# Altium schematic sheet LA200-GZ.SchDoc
size A1
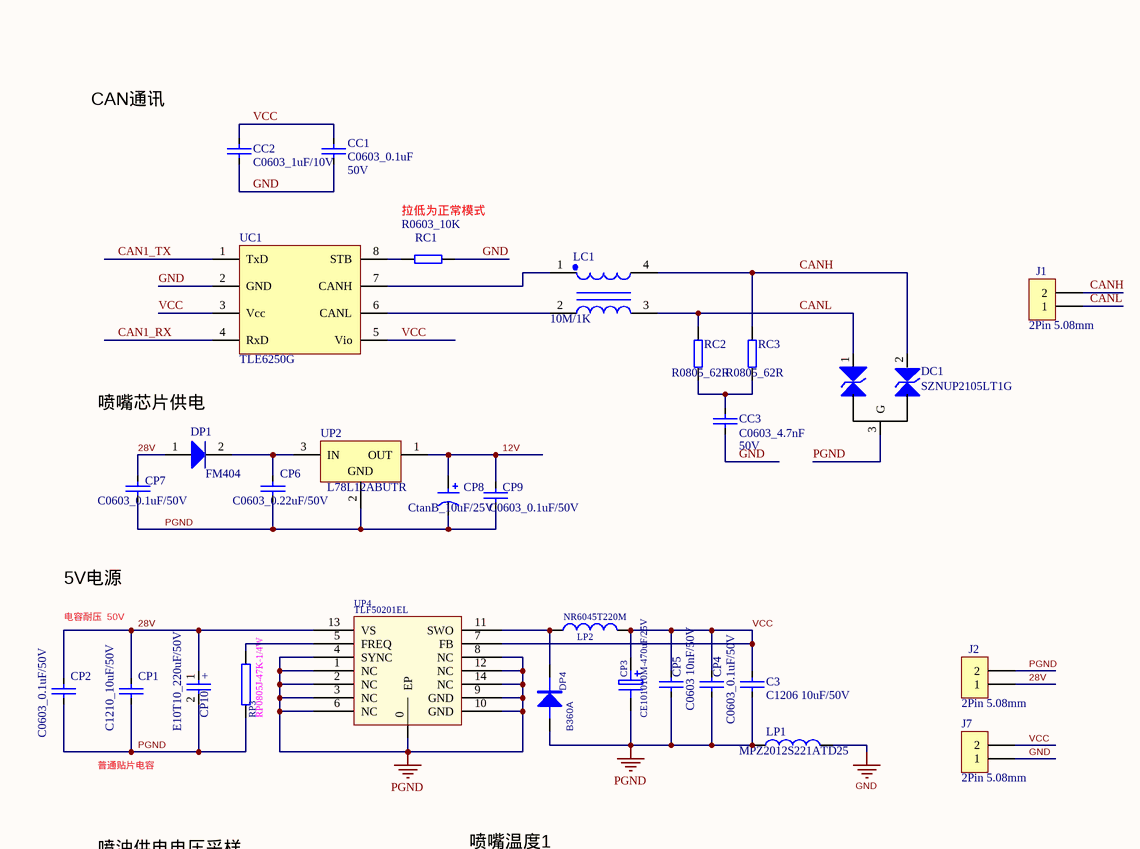
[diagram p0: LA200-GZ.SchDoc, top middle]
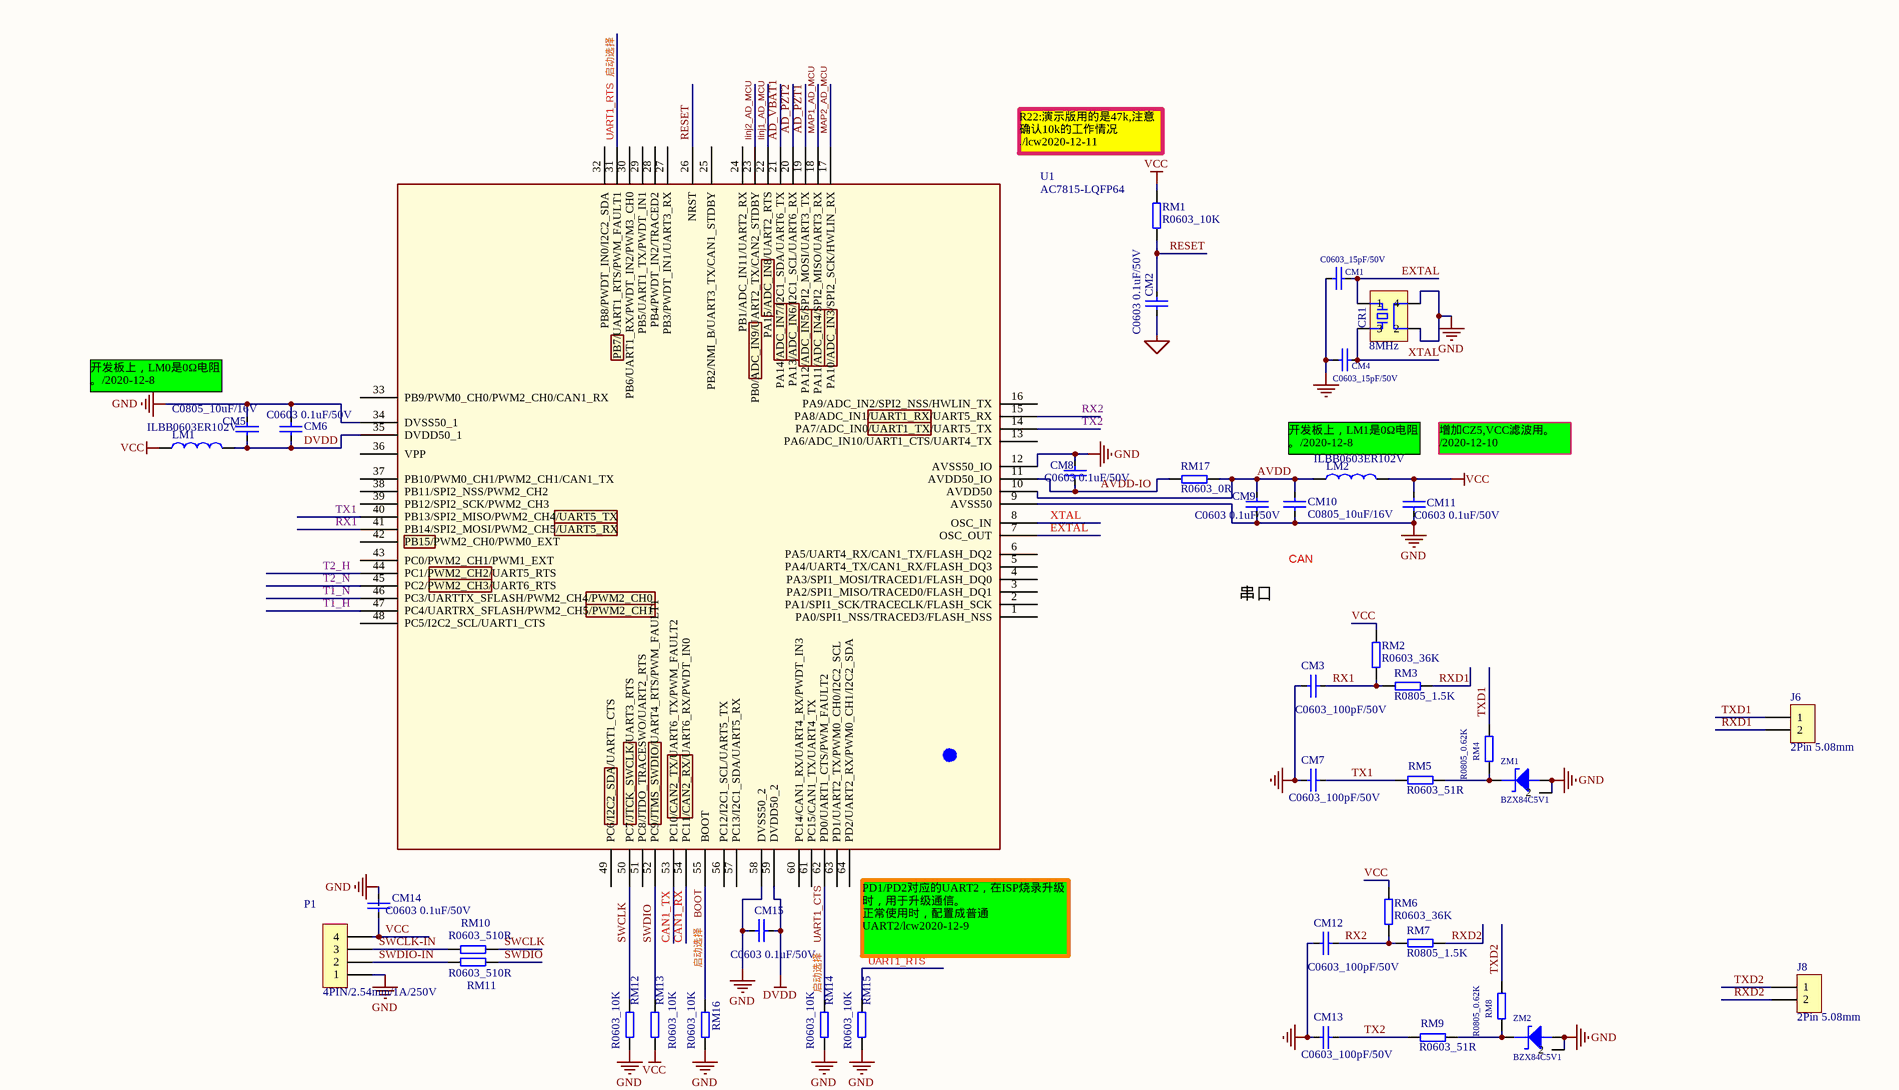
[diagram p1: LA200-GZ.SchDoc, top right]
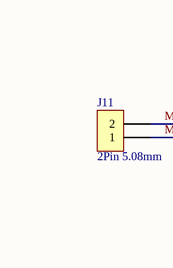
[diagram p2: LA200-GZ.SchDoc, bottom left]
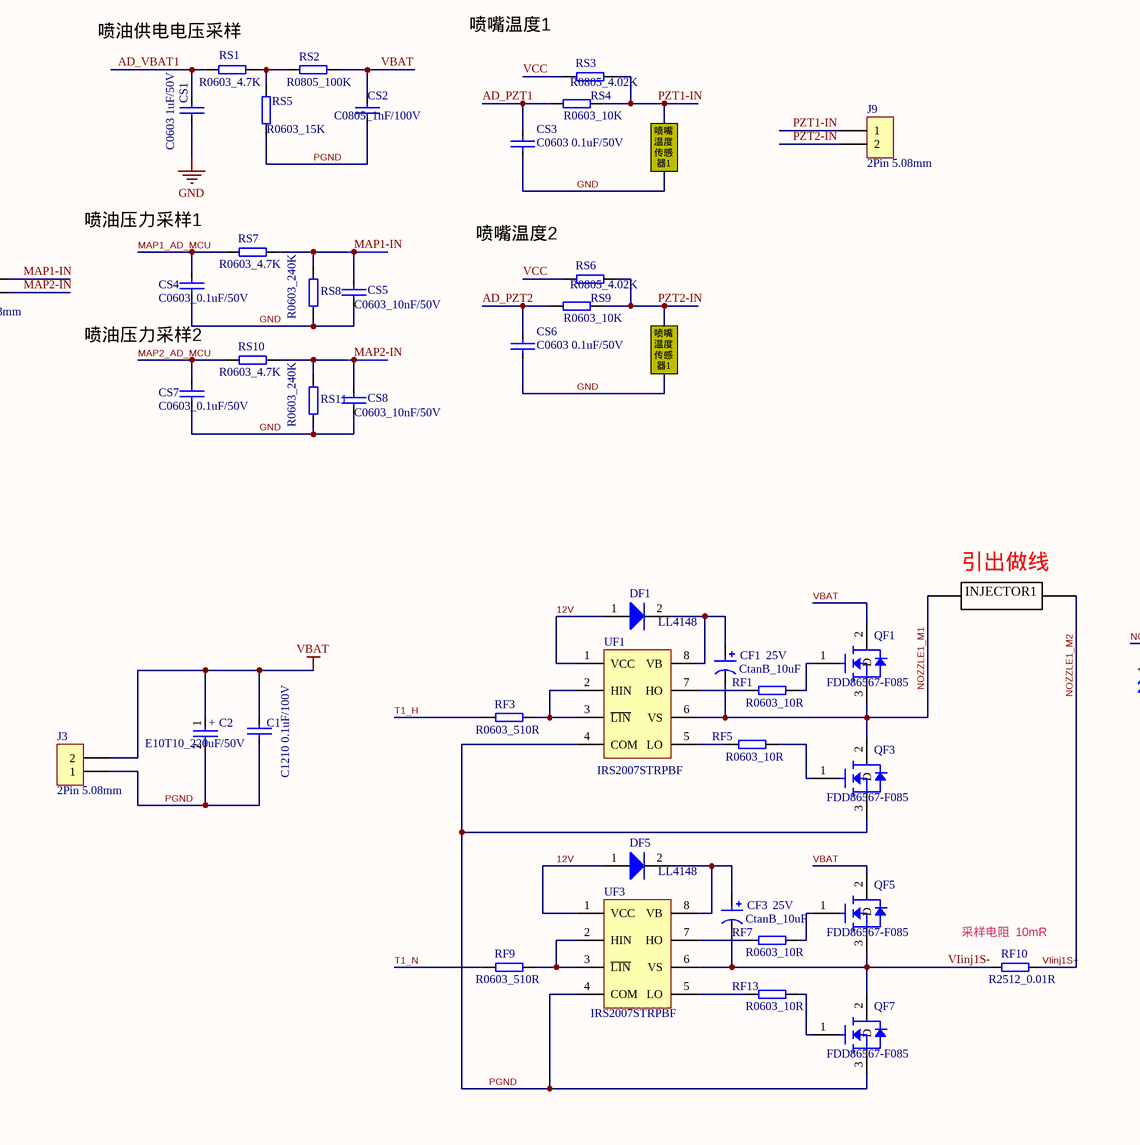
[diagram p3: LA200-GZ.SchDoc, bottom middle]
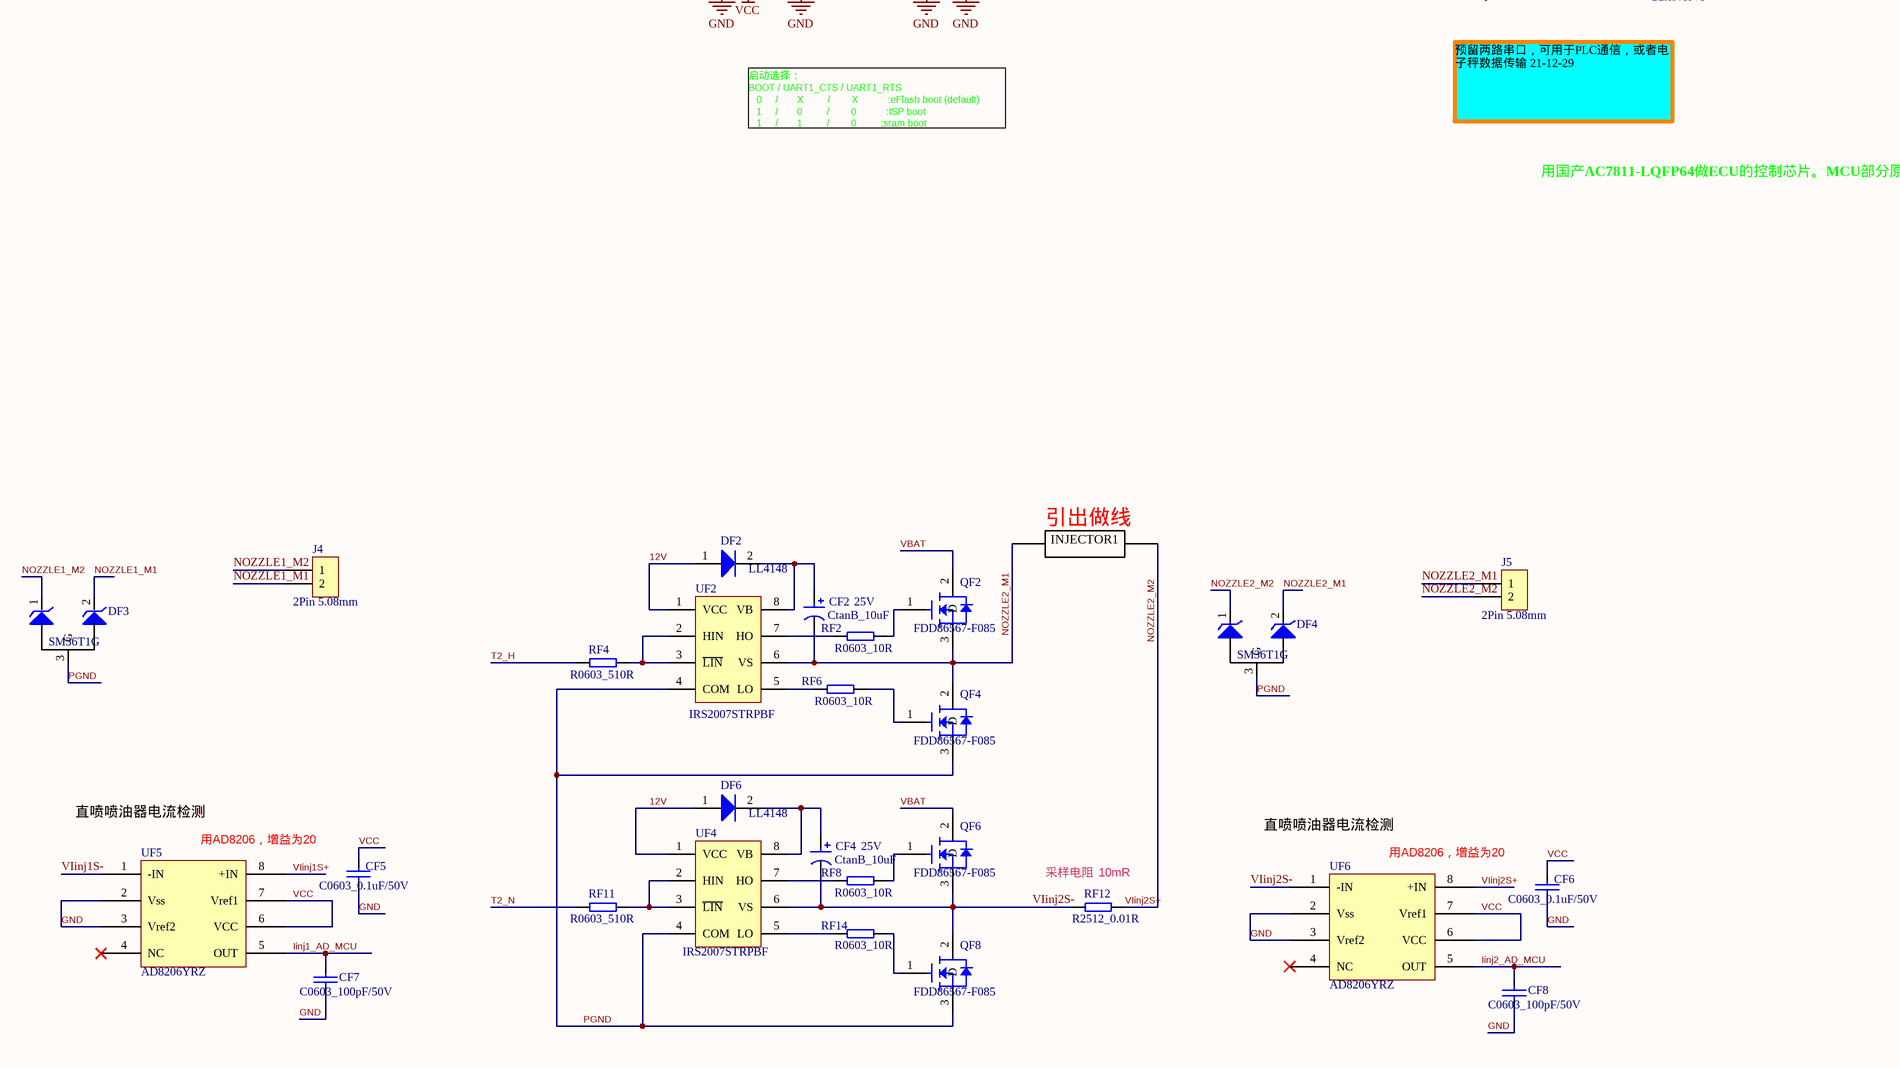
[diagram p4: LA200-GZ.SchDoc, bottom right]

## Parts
C1  C1210 0.1uF/100V  [C1210]
C2  E10T10_220uF/50V  [E10T10]
C3  C1206 10uF/50V  [C1206]
CC1  Voltage: 50V  [C0603]  (hidden comment: C0603_0.1uF)
CC2  C0603_1uF/10V  [C0603]
CC3  Voltage: 50V  [C0603]  (hidden comment: C0603_4.7nF)
CF1  Voltage: 25V  [CTANB]  (hidden comment: CtanB_10uF)
CF2  Voltage: 25V  [CTANB]  (hidden comment: CtanB_10uF)
CF3  Voltage: 25V  [CTANB]  (hidden comment: CtanB_10uF)
CF4  Voltage: 25V  [CTANB]  (hidden comment: CtanB_10uF)
CF5  C0603_0.1uF/50V  [C0603]
CF6  C0603_0.1uF/50V  [C0603]
CF7  C0603_100pF/50V  [C0603]
CF8  C0603_100pF/50V  [C0603]
CM1  C0603_15pF/50V  [C0603]
CM2  C0603 0.1uF/50V  [C0603]
CM3  C0603_100pF/50V  [C0603]
CM4  C0603_15pF/50V  [C0603]
CM5  C0805_10uF/16V  [C0805]
CM6  C0603 0.1uF/50V  [C0603]
CM7  C0603_100pF/50V  [C0603]
CM8  C0603 0.1uF/50V  [C0603]
CM9  C0603 0.1uF/50V  [C0603]
CM10  C0805_10uF/16V  [C0805]
CM11  C0603 0.1uF/50V  [C0603]
CM12  C0603_100pF/50V  [C0603]
CM13  C0603_100pF/50V  [C0603]
CM14  C0603 0.1uF/50V  [C0603]
CM15  C0603 0.1uF/50V  [C0603]
CP1  C1210_10uF/50V  [C1210]
CP2  C0603_0.1uF/50V  [C0603]
CP3  CE101010M-470uF/25V  [E10T10]
CP4  C0603_0.1uF/50V  [C0603]
CP5  C0603 10nF/50V  [C0603]
CP6  C0603_0.22uF/50V  [C0603]
CP7  C0603_0.1uF/50V  [C0603]
CP8  CtanB_10uF/25V  [CTANB]
CP9  C0603_0.1uF/50V  [C0603]
CP10  E10T10_220uF/50V  [E10T10]
CR1  8MHz  [5.0*3.2*0.9mm AB]
CS1  C0603 1uF/50V  [C0603]
CS2  C0805_1nF/100V  [C0805]
CS3  C0603 0.1uF/50V  [C0603]
CS4  C0603_0.1uF/50V  [C0603]
CS5  C0603_10nF/50V  [C0603]
CS6  C0603 0.1uF/50V  [C0603]
CS7  C0603_0.1uF/50V  [C0603]
CS8  C0603_10nF/50V  [C0603]
DC1  SZNUP2105LT1G  [SOT-23]
DF1  LL4148  [SOD-80]
DF2  LL4148  [SOD-80]
DF3  SM36T1G  [SOT-23]
DF4  SM36T1G  [SOT-23]
DF5  LL4148  [SOD-80]
DF6  LL4148  [SOD-80]
DP1  FM404  [D0-214AC]
DP4  B360A  [SMA-DIODE]
J1  2Pin 5.08mm  [CONN-TH_2P-P5.08_DB128L-5.08-2P]
J2  2Pin 5.08mm  [CONN-TH_2P-P5.08_DB128L-5.08-2P]
J3  2Pin 5.08mm  [CONN-TH_2P-P5.08_DB128L-5.08-2P]
J4  2Pin 5.08mm  [CONN-TH_2P-P5.08_DB128L-5.08-2P]
J5  2Pin 5.08mm  [CONN-TH_2P-P5.08_DB128L-5.08-2P]
J6  2Pin 5.08mm  [CONN-TH_2P-P5.08_DB128L-5.08-2P]
J7  2Pin 5.08mm  [CONN-TH_2P-P5.08_DB128L-5.08-2P]
J8  2Pin 5.08mm  [CONN-TH_2P-P5.08_DB128L-5.08-2P]
J9  2Pin 5.08mm  [CONN-TH_2P-P5.08_DB128L-5.08-2P]
J11  2Pin 5.08mm  [CONN-TH_2P-P5.08_DB128L-5.08-2P]
LC1  10M/1K  [ACT45B]
LM1  ILBB0603ER102V  [L0603]
LM2  ILBB0603ER102V  [L0603]
LP1  MPZ2012S221ATD25  [L 0805]
LP2  NR6045T220M  [L_6045]
P1  4PIN/2.54mm/1A/250V  [IDC-SIP-4P-2.54]
QF1  FDD86567-F085  [TO-252-3]
QF2  FDD86567-F085  [TO-252-3]
QF3  FDD86567-F085  [TO-252-3]
QF4  FDD86567-F085  [TO-252-3]
QF5  FDD86567-F085  [TO-252-3]
QF6  FDD86567-F085  [TO-252-3]
QF7  FDD86567-F085  [TO-252-3]
QF8  FDD86567-F085  [TO-252-3]
RC1  R0603_10K  [R0603]
RC2  R0805_62R  [R0805]
RC3  R0805_62R  [R0805]
RF1  R0603_10R  [R0603]
RF2  R0603_10R  [R0603]
RF3  R0603_510R  [R0603]
RF4  R0603_510R  [R0603]
RF5  R0603_10R  [R0603]
RF6  R0603_10R  [R0603]
RF7  R0603_10R  [R0603]
RF8  R0603_10R  [R0603]
RF9  R0603_510R  [R0603]
RF10  R2512_0.01R  [R2512]
RF11  R0603_510R  [R0603]
RF12  R2512_0.01R  [R2512]
RF13  R0603_10R  [R0603]
RF14  R0603_10R  [R0603]
RM1  R0603_10K  [R0603]
RM2  R0603_36K  [R0603]
RM3  R0805_1.5K  [R0805]
RM4  R0805_0.62K  [R0805]
RM5  R0603_51R  [R0603]
RM6  R0603_36K  [R0603]
RM7  R0805_1.5K  [R0805]
RM8  R0805_0.62K  [R0805]
RM9  R0603_51R  [R0603]
RM10  R0603_510R  [R0603]
RM11  R0603_510R  [R0603]
RM12  R0603_10K  [R0603]
RM13  R0603_10K  [R0603]
RM14  R0603_10K  [R0603]
RM15  R0603_10K  [R0603]
RM16  R0603_10K  [R0603]
RM17  R0603_0R  [R0603]
RP3  RP0805J-47K-1/4W  [0805_R]
RS1  R0603_4.7K  [R0603]
RS2  R0805_100K  [R0805]
RS3  R0805_4.02K  [R0805]
RS4  R0603_10K  [R0603]
RS5  R0603_15K  [R0603]
RS6  R0805_4.02K  [R0805]
RS7  R0603_4.7K  [R0603]
RS8  R0603_240K  [R0603]
RS9  R0603_10K  [R0603]
RS10  R0603_4.7K  [R0603]
RS11  R0603_240K  [R0603]
U1  AC7815-LQFP64  [LQFP-64_L10.0-W10.0-P0.50-LS12.0-BL-EP5.3]
UC1  TLE6250G  [PG-DSO-8]
UF1  IRS2007STRPBF  [SOIC-8L]
UF2  IRS2007STRPBF  [SOIC-8L]
UF3  IRS2007STRPBF  [SOIC-8L]
UF4  IRS2007STRPBF  [SOIC-8L]
UF5  AD8206YRZ  [SO-8_NB]
UF6  AD8206YRZ  [SO-8_NB]
UP2  L78L12ABUTR  [SOT-89]
UP4  TLF50201EL  [SSOP14-EP2]
ZM1  BZX84C5V1  [SOT-23AK]
ZM2  BZX84C5V1  [SOT-23AK]

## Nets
DVDD: CM5.2 CM6.1 CM15.2 LM1.2 U1.35(DVDD50_1) U1.59(DVDD50_2)
GND: CC1.2 CC2.1 CC3.2 CF5.2 CF6.2 CF7.2 CF8.2 CM1.2 CM2.1 CM3.1 CM4.2 CM5.1 CM6.2 CM7.1 CM8.1 CM9.2 CM10.2 CM11.2 CM12.1 CM13.1 CM14.1 CM15.1 CR1.2 CR1.4 CS1.2 CS3.2 CS4.2 CS5.2 CS6.2 CS7.2 CS8.2 J7.1 LP1.2 P1.1 RC1.2 RM12.1 RM14.1 RM15.1 RM16.1 RS8.1 RS11.1 U1.9(AVSS50) U1.12(AVSS50_IO) U1.34(DVSS50_1) U1.58(DVSS50_2) UC1.2(GND) UF5.2(Vss) UF5.3(Vref2) UF6.2(Vss) UF6.3(Vref2) ZM1.A ZM1.NC(2) ZM2.A ZM2.NC(2)
PGND: C1.2 C2.2 C3.2 CP1.2 CP2.2 CP3.2 CP4.2 CP5.2 CP6.2 CP7.2 CP8.2 CP9.2 CP10.2 CS2.2 DC1.3(G) DF3.3(G) DF4.3(G) DP4.A J2.2 J3.1 LP1.1 QF3.3(S) QF4.3(S) QF7.3(S) QF8.3(S) RP3.1 RS5.1 UF1.4(COM) UF2.4(COM) UF3.4(COM) UF4.4(COM) UP2.2(GND) UP4.0(EP) UP4.1(NC) UP4.2(NC) UP4.3(NC) UP4.4(SYNC) UP4.6(NC) UP4.8(NC) UP4.9(GND) UP4.10(GND) UP4.12(NC) UP4.14(NC)
VBAT: C1.1 C2.1 CS2.1 J3.2 QF1.2(D) QF2.2(D) QF5.2(D) QF6.2(D) RS2.2
VCC: C3.1 CC1.1 CC2.2 CF5.1 CF6.1 CM11.1 CM14.2 CP3.1 CP4.1 CP5.1 J7.2 LM1.1 LM2.2 LP2.2 P1.4 RM1.2 RM2.2 RM6.2 RM13.1 RS3.1 RS6.1 UC1.3(Vcc) UC1.5(Vio) UF5.6(VCC) UF5.7(Vref1) UF6.6(VCC) UF6.7(Vref1) UP4.7(FB)
12V: CP8.1 CP9.1 DF1.1 DF2.1 DF5.1 DF6.1 UF1.1(VCC) UF2.1(VCC) UF3.1(VCC) UF4.1(VCC) UP2.1(OUT)
28V: CP1.1 CP2.1 CP7.1 CP10.1 DP1.1 J2.1 UP4.13(VS)
AD_PZT1: CS3.1 RS4.1 U1.19(PA12/ADC_IN5/SPI2_MOSI/UART3_TX)
AD_PZT2: CS6.1 RS9.1 U1.20(PA13/ADC_IN6/I2C1_SCL/UART6_RX)
AD_VBAT1: CS1.1 RS1.1 U1.21(PA14/ADC_IN7/I2C1_SDA/UART6_TX)
AVDD: CM9.1 CM10.1 LM2.1 RM17.2 U1.10(AVDD50)
AVDD-IO: CM8.2 RM17.1 U1.11(AVDD50_IO)
BOOT: RM16.2 U1.55(BOOT)
CAN1_RX: U1.54(PC11/CAN2_RX/UART6_RX/PWDT_IN0) UC1.4(RxD)
CAN1_TX: U1.53(PC10/CAN2_TX/UART6_TX/PWM_FAULT2) UC1.1(TxD)
CANH: DC1.2 J1.2 LC1.4 RC3.2
CANL: DC1.1 J1.1 LC1.3 RC2.2
EXTAL: CM1.1 CR1.1 U1.7(OSC_OUT)
Iinj1_AD_MCU: CF7.1 U1.22(PA15/ADC_IN8/UART2_RTS) UF5.5(OUT)
Iinj2_AD_MCU: CF8.1 U1.23(PB0/ADC_IN9/UART2_TX/CAN2_STDBY) UF6.5(OUT)
MAP1-IN: CS5.1 J11.2 RS7.2 RS8.2
MAP1_AD_MCU: CS4.1 RS7.1 U1.18(PA11/ADC_IN4/SPI2_MISO/UART3_RX)
MAP2-IN: CS8.1 J11.1 RS10.2 RS11.2
MAP2_AD_MCU: CS7.1 RS10.1 U1.17(PA10/ADC_IN3/SPI2_SCK/HWLIN_RX)
NOZZLE1_M1: CF1.2 DF3.2 J4.2 QF1.3(S) QF3.2(D) UF1.6(VS)
NOZZLE1_M2: DF3.1 J4.1 RF10.2 UF5.8(+IN)  [also labelled VIinj1S+]
NOZZLE2_M1: CF2.2 DF4.2 J5.1 QF2.3(S) QF4.2(D) UF2.6(VS)
NOZZLE2_M2: DF4.1 J5.2 RF12.2 UF6.8(+IN)  [also labelled VIinj2S+]
PZT1-IN: J9.1 RS3.2 RS4.2
PZT2-IN: J9.2 RS6.2 RS9.2
RESET: CM2.2 RM1.1 U1.26(NRST)
RX1: CM3.2 RM2.1 RM3.1 U1.41(PB14/SPI2_MOSI/PWM2_CH5/UART5_RX)
RX2: CM12.2 RM6.1 RM7.1 U1.15(PA8/ADC_IN1/UART1_RX/UART5_RX)
RXD1: J6.2 RM3.2
RXD2: J8.2 RM7.2
SWCLK: RM10.2 RM12.2 U1.50(PC7/JTCK_SWCLK/UART3_RTS)
SWCLK-IN: P1.3 RM10.1
SWDIO: RM11.2 RM13.2 U1.52(PC9/JTMS_SWDIO/UART4_RTS/PWM_FAULT1)
SWDIO-IN: P1.2 RM11.1
T1_H: RF3.1 U1.47(PC4/UARTRX_SFLASH/PWM2_CH5/PWM2_CH1)
T1_N: RF9.1 U1.46(PC3/UARTTX_SFLASH/PWM2_CH4/PWM2_CH0)
T2_H: RF4.1 U1.44(PC1/PWM2_CH2/UART5_RTS)
T2_N: RF11.1 U1.45(PC2/PWM2_CH3/UART6_RTS)
TX1: CM7.2 RM5.1 U1.40(PB13/SPI2_MISO/PWM2_CH4/UART5_TX)
TX2: CM13.2 RM9.1 U1.14(PA7/ADC_IN0/UART1_TX/UART5_TX)
TXD1: J6.1 RM4.2
TXD2: J8.1 RM8.2
UART1_CTS: RM14.2 U1.62(PD0/UART1_CTS/PWM_FAULT2)
UART1_RTS: RM15.2 U1.31(PB7/UART1_RTS/PWM_FAULT1)
VIinj1S-: CF3.2 QF5.3(S) QF7.2(D) RF10.1 UF3.6(VS) UF5.1(-IN)
VIinj2S-: CF4.2 QF6.3(S) QF8.2(D) RF12.1 UF4.6(VS) UF6.1(-IN)
XTAL: CM4.1 CR1.3 U1.8(OSC_IN)
NetCC3_1: CC3.1 RC2.1 RC3.1
NetCF1_1: CF1.1 DF1.2 UF1.8(VB)
NetCF2_1: CF2.1 DF2.2 UF2.8(VB)
NetCF3_1: CF3.1 DF5.2 UF3.8(VB)
NetCF4_1: CF4.1 DF6.2 UF4.8(VB)
NetCP6_1: CP6.1 DP1.2 UP2.3(IN)
NetDP4_K: DP4.K LP2.1 UP4.11(SWO)
NetLC1_1: LC1.1 UC1.7(CANH)
NetLC1_2: LC1.2 UC1.6(CANL)
NetQF1_1: QF1.1 RF1.2
NetQF2_1: QF2.1 RF2.2
NetQF3_1: QF3.1 RF5.2
NetQF4_1: QF4.1 RF6.2
NetQF5_1: QF5.1 RF7.2
NetQF6_1: QF6.1 RF8.2
NetQF7_1: QF7.1 RF13.2
NetQF8_1: QF8.1 RF14.2
NetRC1_1: RC1.1 UC1.8(STB)
NetRF1_1: RF1.1 UF1.7(HO)
NetRF2_1: RF2.1 UF2.7(HO)
NetRF3_2: RF3.2 UF1.2(HIN) UF1.3(~{LIN})
NetRF4_2: RF4.2 UF2.2(HIN) UF2.3(~{LIN})
NetRF5_1: RF5.1 UF1.5(LO)
NetRF6_1: RF6.1 UF2.5(LO)
NetRF7_1: RF7.1 UF3.7(HO)
NetRF8_1: RF8.1 UF4.7(HO)
NetRF9_2: RF9.2 UF3.2(HIN) UF3.3(~{LIN})
NetRF11_2: RF11.2 UF4.2(HIN) UF4.3(~{LIN})
NetRF13_1: RF13.1 UF3.5(LO)
NetRF14_1: RF14.1 UF4.5(LO)
NetRM4_1: RM4.1 RM5.2 ZM1.K
NetRM8_1: RM8.1 RM9.2 ZM2.K
NetRP3_2: RP3.2 UP4.5(FREQ)
NetRS1_2: RS1.2 RS2.1 RS5.2

Not connected (* = marked no-connect by the designer): U1 1(PA0/SPI1_NSS/TRACED3/FLASH_NSS) 2(PA1/SPI1_SCK/TRACECLK/FLASH_SCK) 3(PA2/SPI1_MISO/TRACED0/FLASH_DQ1) 4(PA3/SPI1_MOSI/TRACED1/FLASH_DQ0) 5(PA4/UART4_TX/CAN1_RX/FLASH_DQ3) 6(PA5/UART4_RX/CAN1_TX/FLASH_DQ2) 13(PA6/ADC_IN10/UART1_CTS/UART4_TX) 16(PA9/ADC_IN2/SPI2_NSS/HWLIN_TX) 24(PB1/ADC_IN11/UART2_RX) 25(PB2/NMI_B/UART3_TX/CAN1_STDBY) 27(PB3/PWDT_IN1/UART3_RX) 28(PB4/PWDT_IN2/TRACED2) 29(PB5/UART1_TX/PWDT_IN1) 30(PB6/UART1_RX/PWDT_IN2/PWM3_CH0) 32(PB8/PWDT_IN0/I2C2_SDA) 33(PB9/PWM0_CH0/PWM2_CH0/CAN1_RX) 36(VPP) 37(PB10/PWM0_CH1/PWM2_CH1/CAN1_TX) 38(PB11/SPI2_NSS/PWM2_CH2) 39(PB12/SPI2_SCK/PWM2_CH3) 42(PB15/PWM2_CH0/PWM0_EXT) 43(PC0/PWM2_CH1/PWM1_EXT) 48(PC5/I2C2_SCL/UART1_CTS) 49(PC6/I2C2_SDA/UART1_CTS) 51(PC8/JTDO_TRACESWO/UART2_RTS) 56(PC12/I2C1_SCL/UART5_TX) 57(PC13/I2C1_SDA/UART5_RX) 60(PC14/CAN1_RX/UART4_RX/PWDT_IN3) 61(PC15/CAN1_TX/UART4_TX) 63(PD1/UART2_TX/PWM0_CH0/I2C2_SCL) 64(PD2/UART2_RX/PWM0_CH1/I2C2_SDA); UF5 4(NC)*; UF6 4(NC)*

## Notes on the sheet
- 启动选择
- R22:演示版用的是47k,注意确认10k的工作情况./lcw2020-12-11
- CAN通讯
- 开发板上，LM0是0Ω电阻。/2020-12-8
- 拉低为正常模式
- (near LM2) 开发板上，LM1是0Ω电阻。/2020-12-8
- 增加CZ5,VCC滤波用。/2020-12-10
- CAN
- 喷嘴芯片供电
- 串口
- 电容耐压  50V
- 5V电源
- 普通贴片电容
- (near U1) PD1/PD2对应的UART2，在ISP烧录升级时，用于升级通信。
  正常使用时，配置成普通UART2/lcw2020-12-9
- (near RM14) 启动选择
- 喷油供电电压采样
- 喷嘴温度1
- 喷油压力采样1
- 喷嘴温度
  传感器1
- 启动选择：
  BOOT / UART1_CTS / UART1_RTS
  0     /       X         /        X           :eFlash boot (default)
  1     /       0         /        0           :ISP boot
  1     /       1         /        0         :sram boot
  1     /       0        /         1        :serial flash boot
- 预留两路串口，可用于PLC通信，或者电子秤数据传输 21-12-29
- 喷嘴温度2
- 用国产AC7811-LQFP64做ECU的控制芯片。MCU部分原理图/2021-3-5
- 喷油压力采样2
- INJECTOR1
- 引出做线
- 直喷喷油器电流检测
- (near RF10) 采样电阻
- (near RF10) 10mR
- (near UF5) 用AD8206，增益为20
- (near RF12) 采样电阻
- (near RF12) 10mR
- (near UF6) 用AD8206，增益为20

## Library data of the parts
C1 = 3170014005: C1210 0.1uF/50V 10%; Part Number1: 03172540005; Manufacturer: YAGEO; Manufacture no: CC1210KRX7R9BB104; Voltage: 100V; Tolerance: 0.1; Type: 贴片电容
C2 = 3172690040: E10T10 220uF/50V 20%; Part Number1: 03172690040; Manufacturer: LELON; Voltage: 50V; Tolerance: 0.2; Type: 铝电解电容
C3 = 3172530019: C1206 10uF/50V  10%; Part Number1: 03172530019; Manufacturer: YAGEO; Voltage: 50V; Tolerance: 0.1; Type: 贴片电容
CC1 = 3170011015: C0603 0.1uF/50V 10%; Part Number1: 03172510014; Manufacturer: YAGEO; Manufacture no: CC0603KRX7R9BB104; Tolerance: 0.1
CC2 = 3170011015: C0603 0.1uF/50V 10%; Part Number1: 03172510014; Manufacturer: YAGEO; Manufacture no: CC0603KRX7R9BB104; Voltage: 10V; Tolerance: 0.1
CC3 = 3170011009: C0603 4.7nF/50V 5% X7R; Part Number1: 03172410008; Manufacturer: YAGEO; Manufacture no: CC0603JRX7R9BB472; Tolerance: 0.1
CF1-CF4 = 3172690034: CtanB(1210) 10uF/25V 10%; Part Number1: 03172690034; Manufacturer: AVX; Manufacture no: TAJB106K025RNJ; Tolerance: 0.1
CF5 CF6 CM2 CM6 CM8 CM9 CM11 CM14 CM15 CP2 CP4 CP7 CP9 CS3 CS4 CS6 CS7 = 3170011015: C0603 0.1uF/50V 10%; Part Number1: 03172510014; Manufacturer: YAGEO; Manufacture no: CC0603KRX7R9BB104; Voltage: 50V; Tolerance: 0.1
CF7 CF8 CM3 CM7 CM12 CM13 = 3170011003: C0603 100pF/50V 5%; Part Number1: 03172410002; Manufacturer: YAGEO/Fenghua; Manufacture no: CC0603JRNPO9BN101; Voltage: 50V; Tolerance: 0.05
CM1 CM4 = 3172510040: C0603 15pF/50V 10%; Part Number1: 03172510040; Manufacturer: YAGEO; Voltage: 50V; Tolerance: 0.1
CM5 CM10 = 3170012008: C0805 10uF/16V 10%; Part Number1: 03172520008; Manufacturer: YAGEO; Manufacture no: CC0805KRX5R7BB106; Voltage: 16V; Tolerance: 0.1
CP1 = 3170014011: C1210 10uF/50V 10%; Part Number1: 03172540011; Manufacturer: murata; Manufacture no: GRM32ER71H106KA12L; Voltage: 50V; Tolerance: 0.1
CP3 = ELECTRO1: 条形码: VEJ471M1ETR-1010; 物料编码: EPCA01006610
CP5 CS5 CS8 = 3170011011: C0603 10nF/50V  10%; Part Number1: 03172510010; Manufacturer: YAGEO; Manufacture no: CC0603KRX7R9BB103; Voltage: 50V; Tolerance: 0.1
CP6 = 3172510028: C0603 0.22uF/50V 10%; Part Number1: 03172510028; Manufacturer: YAGEO; Voltage: 50V; Tolerance: 0.1
CP8 = 3172690034: CtanB(1210) 10uF/25V 10%; Part Number1: 03172690034; Manufacturer: AVX; Manufacture no: TAJB106K025RNJ; Voltage: 25V; Tolerance: 0.1
CP10 = 3172690040: E10T10 220uF/50V 20%; Part Number1: 03172690040; Manufacturer: LELON; Voltage: 50V; Tolerance: 0.2
CR1 = 53120010024: 5.0*3.2*0.9mm AB 8MHz; Manufacturer: TXC; Type: 晶振
CS1 = 3172510036: C0603 1uF/50V 10%; Part Number1: 03172510036; Manufacturer: YAGEO; Voltage: 50V; Tolerance: 0.1
CS2 = 3172520028: C0805 1nF/100V 10%; Part Number1: 03172520028; Manufacturer: YAGEO; Voltage: 100V; Tolerance: 0.1
DC1 = 3110050073: SOT-23 SZNUP2105LT1G; Part Number1: 03110050073; Manufacturer: ON; ProductNumber: GSOT08C/Vishay; Voltage: 24V; Power: 350W
DF1 DF2 DF5 DF6 = 3110010015: SOD-80  LL4148 2A/75V; Part Number1: 03110010015; Manufacturer: VISHA; Current: 2A; Voltage: 75V
DF3 DF4 = 3110050074: SOT-23 SM36T1G; Part Number1: 03110050074; Manufacturer: ON; ProductNumber: GSOT08C/Vishay; Voltage: 36V; Power: 300W
DP1 = 13110010013: D0-214AC FM404; Part Number1: 53110010013; Manufacturer: LRC; Current: 1A; Voltage: 400V
DP4 = DIODE: 60V,1A,肖特基二极管
J1-J9 J11 = 31900010141: 691311500002 2Pin 5.08mm 公头; Part Number1: 53190010141; Manufacturer: WE
LC1 = 3180020022: ACT45B-510-2P-TL  10M/1K/0.2A; Part Number1: 03180020022; Manufacturer: TDK; Current: 0.2A; Tolerance: 20%; DCR: 1R
LM1 LM2 = 3180020002: L0603 ILBB0603ER102V; Part Number1: 03180020002; Manufacturer: Vishay; Current: 0.1A; Tolerance: 100M/1K; DCR: 0.6R
LP1 = 53180020011: L0805 MPZ2012S221ATD25; Manufacturer: TDK; Current: 3A; Tolerance: 25%; DCR: 0.04Ω
LP2 = Inductor: 22uH/1.9A; 条形码: YKNR6045-220; 物料编码: EPLA03000310
P1 = 3190010008: 直针插座 CWF25404D180 4PIN/2.54mm/1A/250V; Part Number1: 03190010008; Manufacturer: CSCONN 德科泰
QF1-QF8 = 53110022012: TO-252-3 FDD86567-F085 60V/100A; Manufacturer: ON; Current: 100A; Voltage: 60V; DCR: 3.2mR
RC1 RM12-RM16 = 3160030053: R0603 1/10w 10K 1%; Part Number1: 03162310053; Manufacturer: YAGEO; Manufacture no: RC0603FR-0710KL; Tolerance: 0.01
RC2 RC3 = 3160050016: R0805 1/8w10R 1%; Part Number1: 03162320016; Manufacturer: YAGEO; Manufacture no: RC0805FR-0710RL; Power: 1/8w; Tolerance: 0.01
RF1 RF2 RF5-RF8 RF13 RF14 = 3160030193: R0603 1/10w  10R 1%; Part Number1: 03162310193; Manufacturer: YAGEO; Manufacture no: RC0603FR-0710RL; Tolerance: 0.01
RF3 RF4 RF9 RF11 RM10 RM11 = 3160030020: R0603  1/10w 510R 1%; Part Number1: 03162310020; Manufacturer: YAGEO; Manufacture no: RC0603FR-07510RL; Tolerance: 0.01
RF10 RF12 = 3162380033: R2512 1W 0.01R 1%; Part Number1: 03162380033; Manufacturer: YAGEO; Tolerance: 0.01
RM1 RS4 RS9 = 3160030053: R0603 1/10w 10K; Part Number1: 03162310053; Manufacturer: YAGEO; Manufacture no: RC0603FR-0710KL; Tolerance: 0.01
RM2 RM6 = 3160030087: R0603 1/10w  36K 1%; Part Number1: 03162310087; Manufacturer: YAGEO; Manufacture no: RC0603FR-0736KL; Tolerance: 0.01
RM3 RM7 = 13162320038: R0805 1/8w 1.5K 1%最好用1/4w; Manufacturer: YAGEO; Tolerance: 0.01
RM4 RM8 = 3162320027: R0805 1/8w 0.62K 1% 需要1/4w; Part Number1: 03162320027; Manufacturer: YAGEO; Manufacture no: RC0805FR-076K2L; Tolerance: 0.01
RM5 RM9 = 3160030013: R0603  1/10w 51R 1%或100欧; Part Number1: 03162310013; Manufacturer: YAGEO; Manufacture no: RC0603FR-0751RL; Tolerance: 0.01
RM17 = 3160030001: R0603 1/10w 0R 1%; Part Number1: 03162310001; Manufacturer: YAGEO/UNIOHM; Manufacture no: RC0603FR-070RL; Tolerance: 0.01
RP3 = RES2: 汽车级电阻，47kΩ; 条形码: 30PRC0805JR-7W47K; 物料编码: EPRA03010210
RS1 RS7 RS10 = 3160030224: R0603 1/10w  4.7K 1%; Part Number1: 03162310224; Manufacturer: YAGEO; Manufacture no: RC0603FR-074K7L; Tolerance: 0.01
RS2 = 3160050008: R0805 1/8w 100K 1%; Part Number1: 03162320008; Manufacturer: YAGEO; Manufacture no: RC0805FR-07100KL; Tolerance: 0.01
RS3 RS6 = 13162320037: R0805 1/8w 4.02K 1%; Manufacturer: YAGEO; Tolerance: 0.01
RS5 = 3160030062: R0603 1/10w 15K 1%; Part Number1: 03162310062; Manufacturer: YAGEO; Manufacture no: RC0603FR-0715KL; Tolerance: 0.01
RS8 RS11 = 3160030151: R0603 1/10w 240K 1%; Part Number1: 03162310151; Manufacturer: YAGEO; Manufacture no: RC0603FR-07240KL; Tolerance: 0.01
U1 = AC7811-LQFP64
UC1 = 3100050124: PG-DSO-8 TLE9251VSJ; Part Number1: 03100050124; Manufacturer: infineon
UF1-UF4 = 3100050121: SOIC-8L IRS2007STRPBF; Part Number1: 03100050121; Manufacturer: infineon
UF5 UF6 = 3100100010: SO-8_NB AD8206YRZ; Part Number1: 03100100010; Manufacturer: ADI
UP2 = 3100050105: SOT-89 L78L12ABUTR; Part Number1: 03100050105; Manufacturer: ST
UP4 = TLF50201EL: 物料编码: EPIA00000002
ZM1 ZM2 = 3110010088: SOT-23 BZX84C5V1; Part Number1: 13110040088; Manufacturer: ON; Voltage: 225mW; Power: 5.1V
